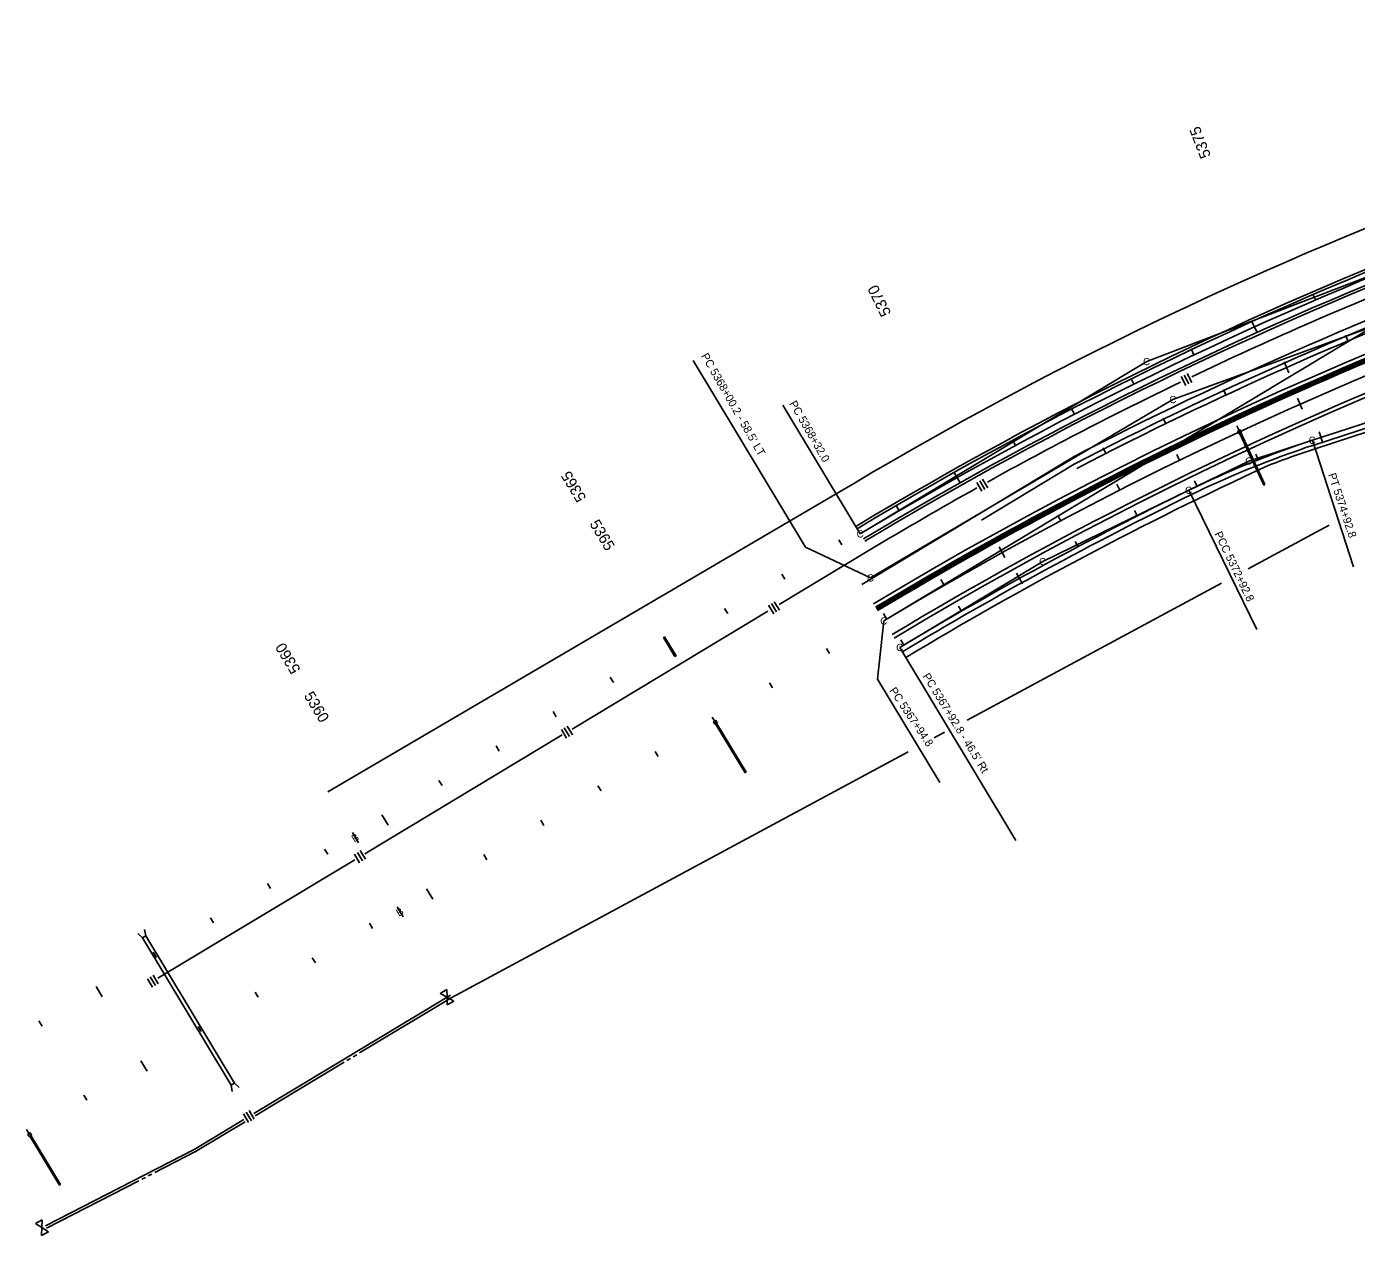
# Model space of a CAD drawing. Extents: x 192699 to 285914, y 194342 to 233219.
# Drawn here: x 279535 to 281530, y 219269 to 221082 of the extents above; entities that cross this region are included whole.
import ezdxf

# ---------------------------------------------------------------- set-up
doc = ezdxf.new("R2010")
doc.units = 0
for name, color, linetype in [('CENT LINE', 7, 'Continuous'), ('CONCRETE', 7, 'Continuous'), ('CURVE DATA', 7, 'Continuous'), ('CURVE LINE', 7, 'Continuous'), ('DRAINAGE', 7, 'Continuous'), ('R-W - CofA', 7, 'Continuous'), ('ROAD', 7, 'Continuous'), ('SHOULDER', 7, 'Continuous'), ('STATIONING1', 7, 'Continuous'), ('STATIONING2', 7, 'Continuous'), ('TEXT', 7, 'Continuous'), ('WRSF', 7, 'Continuous')]:
    doc.layers.add(name, color=color, linetype=linetype)

msp = doc.modelspace()

# ---------------------------------------------------------------- linework, layer by layer
at = {"layer": 'CENT LINE'}
msp.add_line((281463.6, 220461.7), (281631, 220516.2), dxfattribs=at)
for centre, radius, start, end in [((283775, 215280.8), 5730.1, 87.45001, 121.03334), ((283739.9, 215411.7), 5729.9, 111.03691, 121.03638), ((283775, 215280.8), 5788.6, 110.48527, 117.41024), ((281907.3, 219099.2), 1432.9, 108.0419, 116.0389), ((283775, 215280.8), 5683.6, 116.0585, 121.0333)]:
    msp.add_arc(centre, radius, start, end, dxfattribs=at)
at = {"layer": 'CONCRETE'}
for radius, start in [(5752.1, 107.17179), (5748.1, 107.17184)]:
    msp.add_arc((283775, 215280.8), radius, start, 121.03334, dxfattribs=at)
at = {"layer": 'CURVE LINE'}
for p, q in [((280820.9, 220190.8), (282302.5, 221082.2)), ((281683, 220759.7), (281215.2, 220579.8)), ((281749.1, 220703.3), (281254.5, 220522.9)), ((281215.2, 220579.8), (280785.6, 220321.3)), ((281254.5, 220522.9), (280801.1, 220255.3)), ((281368.3, 220430.6), (281463.6, 220461.7)), ((281278.3, 220386.7), (281368.3, 220430.6)), ((281059.3, 220279.9), (281278.3, 220386.7)), ((280844.9, 220150.9), (281059.3, 220279.9))]:
    msp.add_line(p, q, dxfattribs=at)
at = {"layer": 'DRAINAGE'}
for p, q in [((281354.3, 220472.3), (281390.7, 220394.4)), ((281356.2, 220473.2), (281392.5, 220395.2)), ((280490.5, 220165.9), (280492.2, 220166.9)), ((280490.5, 220165.9), (280507.5, 220137.6)), ((280492.2, 220166.9), (280509.3, 220138.6)), ((280507.5, 220137.6), (280509.3, 220138.6)), ((280568.5, 220036.5), (280612.9, 219962.8)), ((280570.2, 220037.5), (280614.6, 219963.9)), ((279842, 219494.4), (279709, 219715.5)), ((279847.1, 219497.5), (279714.1, 219718.6)), ((279540.2, 219417.9), (279584.6, 219344.2)), ((279542, 219418.9), (279586.3, 219345.2))]:
    msp.add_line(p, q, dxfattribs=at)
for points in [[(281353.4, 220471.9), (281357.1, 220473.6), (281355.4, 220477.2), (281351.7, 220475.5)], [(280567.7, 220036), (280571.1, 220038.1), (280569, 220041.5), (280565.6, 220039.4)], [(279539.4, 219417.4), (279542.8, 219419.4), (279540.8, 219422.9), (279537.3, 219420.8)]]:
    msp.add_lwpolyline(points, close=True, dxfattribs=at)
for points in [[(281390.7, 220394.4), (281392.5, 220395.2)], [(280612.9, 219962.8), (280614.6, 219963.9)], [(279702, 219721.9), (279709, 219715.5)], [(279712.4, 219727.7), (279714.2, 219718.4)], [(279714.2, 219718.4), (279709, 219715.5)], [(279842, 219494.4), (279847.2, 219497.4)], [(279843.8, 219485.1), (279842, 219494.4)], [(279854.2, 219491), (279847.2, 219497.4)], [(279584.6, 219344.2), (279586.3, 219345.2)]]:
    msp.add_lwpolyline(points, dxfattribs=at)
at = {"layer": 'R-W - CofA'}
for p, q in [((281271.2, 220559.5), (281278.2, 220546.2)), ((281275.6, 220561.8), (281282.6, 220548.5)), ((281266.7, 220557.2), (281273.7, 220543.8)), ((280964.7, 220401), (280972.4, 220388.1)), ((280969, 220403.5), (280976.7, 220390.6)), ((279987.4, 219934.3), (280749.6, 220381.3)), ((280960.4, 220398.4), (280968.1, 220385.5)), ((281488.7, 220334.3), (281367.4, 220269)), ((280664.1, 220215.5), (280800.1, 220297.3)), ((281327.4, 220247.5), (280945.7, 220042)), ((280656.7, 220219.6), (280664.5, 220206.7)), ((280353.4, 220028.5), (280647.2, 220205.3)), ((280648.1, 220214.5), (280655.9, 220201.6)), ((280652.4, 220217.1), (280660.2, 220204.2)), ((280337.5, 220027.7), (280345.3, 220014.8)), ((280341.8, 220030.3), (280349.6, 220017.4)), ((280346.1, 220032.9), (280353.9, 220020)), ((280912.1, 220023.8), (280896.4, 220015.4)), ((280042.7, 219841.6), (280338.8, 220019.7)), ((280857.5, 219994.4), (280172.9, 219625.9)), ((280027.2, 219841), (280034.9, 219828.1)), ((280031.5, 219843.6), (280039.2, 219830.7)), ((280035.8, 219846.2), (280043.5, 219833.3)), ((279716.5, 219654.1), (279724.2, 219641.2)), ((279720.8, 219656.7), (279728.5, 219643.8)), ((279725.1, 219659.3), (279732.8, 219646.4)), ((280155.8, 219631.9), (280165.8, 219637.9)), ((280166, 219626.3), (280155.8, 219631.9)), ((280165.8, 219637.9), (280166, 219626.3)), ((280166.2, 219614.7), (280166, 219626.3)), ((280166, 219626.3), (280176.1, 219620.6)), ((280176.1, 219620.6), (280166.2, 219614.7)), ((279860.7, 219451.2), (279868.3, 219438.6)), ((279864.9, 219453.7), (279872.6, 219441.1)), ((279869.2, 219456.3), (279876.8, 219443.6)), ((279548.7, 219286.9), (279559, 219292.2)), ((279558.4, 219280.7), (279548.7, 219286.9)), ((279559, 219292.2), (279558.4, 219280.7)), ((279557.9, 219269.1), (279558.4, 219280.7)), ((279568.2, 219274.4), (279557.9, 219269.1)), ((279558.4, 219280.7), (279568.2, 219274.4))]:
    msp.add_line(p, q, dxfattribs=at)
for points in [[(281282.7, 220557), (281282.7, 220557)], [(280976.3, 220399.2), (280976.3, 220399.2)], [(280664.1, 220215.3), (280664.1, 220215.3)], [(280353.4, 220028.5), (280353.4, 220028.5)], [(280043.1, 219841.8), (280043.1, 219841.8)], [(279732.4, 219654.9), (280027.6, 219832.5)], [(279732.4, 219654.9), (279732.4, 219654.9)], [(279876.3, 219452), (280171, 219629.2)], [(280034.8, 219542.7), (280173, 219625.9)], [(279878.4, 219448.6), (280011.6, 219528.8)], [(280015.9, 219531.4), (280021.1, 219534.5)], [(280025.3, 219537), (280030.5, 219540.1)], [(279563.6, 219283.3), (279786.9, 219398.1), (279861.2, 219442.9)], [(279727.7, 219363.3), (279788.8, 219394.7), (279863.2, 219439.5)], [(279565.4, 219279.8), (279703.7, 219350.9)], [(279708.1, 219353.2), (279713.5, 219356)], [(279717.9, 219358.3), (279723.3, 219361)]]:
    msp.add_lwpolyline(points, dxfattribs=at)
for radius, start, end in [(5799.9, 111.03691, 121.03638), (5701.9, 111.7892, 115.5267), (5701.9, 115.717, 118.9921), (5701.9, 119.1747, 121.0364)]:
    msp.add_arc((283739.9, 215411.7), radius, start, end, dxfattribs=at)
at = {"layer": 'ROAD'}
for p, q in [((281465.9, 220454.6), (281633.3, 220509.1)), ((280967.5, 220342), (281106.4, 220426.1))]:
    msp.add_line(p, q, dxfattribs=at)
for centre, radius, start, end in [((283775, 215280.8), 5760.1, 87.45001, 121.03334), ((283775, 215280.8), 5700.1, 87.45, 121.0333), ((283765.6, 215359.2), 5797.2, 110.98651, 120.98597), ((283765.6, 215359.2), 5779.2, 110.98635, 120.98581), ((283775, 215280.8), 5796.1, 110.48527, 117.41317), ((281907.3, 219099.2), 1425.4, 108.0419, 116.0389), ((283775, 215280.8), 5676.1, 116.0585, 121.0333)]:
    msp.add_arc(centre, radius, start, end, dxfattribs=at)
at = {"layer": 'SHOULDER'}
for p, q in [((281467.7, 220448.8), (281635.2, 220503.4)), ((280962.4, 220350.5), (281101.3, 220434.6)), ((280787.9, 220245.6), (280962.4, 220350.6))]:
    msp.add_line(p, q, dxfattribs=at)
for centre, radius, start, end in [((283775, 215280.8), 5706.1, 103.7551, 121.0333), ((283775, 215280.8), 5754.1, 106.67387, 121.03334), ((283765.6, 215359.2), 5801.2, 110.98651, 120.98597), ((283765.6, 215359.2), 5775.2, 110.98635, 120.98581), ((283775, 215280.8), 5806.1, 109.68815, 117.41317), ((281907.3, 219099.2), 1419.4, 108.0419, 111.0954), ((283775, 215280.8), 5666.1, 114.8208, 121.0333)]:
    msp.add_arc(centre, radius, start, end, dxfattribs=at)
at = {"layer": 'STATIONING1'}
for p, q in [((281464.5, 220680.3), (281468.2, 220672.1)), ((281372.9, 220639.8), (281380.6, 220623.5)), ((281513.3, 220619.1), (281516.7, 220610.7)), ((280535, 220581.4), (280703.5, 220301.4)), ((281282.1, 220597.7), (281286, 220589.6)), ((281421.5, 220579.2), (281428.5, 220562.6)), ((281191.9, 220554), (281196, 220546)), ((281330.3, 220537.8), (281333.9, 220529.5)), ((281441.5, 220525), (281448.5, 220508.4)), ((280669.6, 220514.1), (280785.6, 220321.3)), ((281102.6, 220508.7), (281106.8, 220500.8)), ((281239.8, 220494.8), (281243.6, 220486.6)), ((281350.4, 220483.5), (281354.1, 220475.3)), ((281014, 220461.9), (281018.4, 220454.1)), ((281463.6, 220461.7), (281525.3, 220272)), ((281473.7, 220474.5), (281479.3, 220457.3)), ((281150.1, 220450.2), (281154.1, 220442.1)), ((281260.1, 220440.5), (281263.9, 220432.3)), ((281378.9, 220440.9), (281382.3, 220432.5)), ((280926.3, 220413.6), (280935.3, 220398)), ((281286.6, 220400.7), (281290.6, 220392.6)), ((281170.5, 220395.8), (281174.4, 220387.7)), ((281278.3, 220386.7), (281380.2, 220178)), ((280839.5, 220363.7), (280844.1, 220356)), ((281081.7, 220349.6), (281085.8, 220341.6)), ((281196.9, 220356.2), (281201, 220348.2)), ((280703.5, 220301.4), (280801.1, 220255.3)), ((280753.6, 220312.5), (280758.2, 220304.8)), ((280993.7, 220301.9), (281002.2, 220286)), ((281108, 220310), (281112.2, 220302.1)), ((280667.9, 220261), (280672.5, 220253.3)), ((281020, 220262.3), (281028.7, 220246.6)), ((280906.6, 220252.7), (280911, 220244.8)), ((280582.2, 220209.4), (280586.8, 220201.7)), ((280820.4, 220201.9), (280824.9, 220194.1)), ((280932.7, 220213.1), (280937.2, 220205.3)), ((280846.4, 220162.3), (280851.1, 220154.6)), ((280496.6, 220157.8), (280505.8, 220142.4)), ((280735, 220149.6), (280739.7, 220141.9)), ((280410.8, 220106.3), (280415.5, 220098.6)), ((280649.3, 220098.1), (280654, 220090.4)), ((280325.2, 220054.7), (280329.8, 220047)), ((280563.7, 220046.4), (280573, 220031)), ((280239.5, 220003.2), (280244.1, 219995.5)), ((280478, 219995), (280482.6, 219987.2)), ((280153.8, 219951.6), (280158.4, 219943.9)), ((280392.3, 219943.4), (280396.9, 219935.7)), ((280068.1, 219900), (280077.4, 219884.6)), ((280306.6, 219891.8), (280311.2, 219884.1)), ((280220.9, 219840.3), (280225.6, 219832.6)), ((280135.2, 219788.7), (280144.5, 219773.3))]:
    msp.add_line(p, q, dxfattribs=at)
for points in [[(280091, 219762.1), (280095.7, 219754.4)], [(280091, 219762.1), (280100.3, 219746.7)], [(280049.6, 219737.2), (280054.2, 219729.5)], [(279963.9, 219685.6), (279968.5, 219677.9)], [(279878.2, 219634.1), (279882.8, 219626.3)], [(279792.5, 219582.5), (279797.1, 219574.8)], [(279706.8, 219530.9), (279716.1, 219515.5)], [(279621.1, 219479.4), (279625.8, 219471.7)], [(279535.4, 219427.8), (279540.1, 219420.1)]]:
    msp.add_lwpolyline(points, dxfattribs=at)
at = {"layer": 'STATIONING2'}
for points in [[(280024, 219873.5), (280028.6, 219865.8)], [(280024, 219873.5), (280033.3, 219858.1)], [(279982.4, 219848.5), (279987.1, 219840.8)], [(279896.7, 219796.9), (279901.4, 219789.2)], [(279811, 219745.4), (279815.7, 219737.7)], [(279725.4, 219693.8), (279730, 219686.1)], [(279639.7, 219642.3), (279649, 219626.9)], [(279554, 219590.7), (279558.6, 219583)]]:
    msp.add_lwpolyline(points, dxfattribs=at)
at = {"layer": 'TEXT'}
for p, q in [((280820.9, 220190.8), (280811.4, 220103.3)), ((280844.9, 220150.9), (281019, 219861.5)), ((280811.4, 220103.3), (280904.7, 219948.3))]:
    msp.add_line(p, q, dxfattribs=at)
at = {"layer": 'WRSF'}
msp.add_arc((283775, 215280.8), 5750.1, 107.17182, 121.03334, dxfattribs=at)

# ---------------------------------------------------------------- texts
at = {"layer": 'CURVE DATA'}
for s, rotation, p in [('C', 3.0667, (281210, 220574.1)), ('C', 3.0667, (281249.4, 220517.1)), ('C', 3.0667, (281458.4, 220456)), ('C', 3.0667, (281363.2, 220424.9)), ('C', 3.0667, (281273.1, 220381)), ('C', 3.0667, (280780.5, 220315.6)), ('C', 3.0667, (281054.1, 220274.2)), ('C', 3.0667, (280796, 220249.5)), ('C', 3.0667, (280815.8, 220185)), ('C', 3.0667, (280839.8, 220145.2)), ('B', 31.0333, (280026.8, 219858.4)), ('B', 31.0333, (280093.8, 219747))]:
    msp.add_text(s, height=10.8, rotation=rotation, dxfattribs=at).set_placement(p)
at = {"layer": 'STATIONING1'}
for s, rotation, p in [('5375', 111.0333, (281311.7, 220888.3)), ('5370', 116.0333, (280832.3, 220652.3)), ('5365', 121.0333, (280375.4, 220375.3)), ('5360', 121.0333, (279946.9, 220117.7))]:
    msp.add_text(s, height=16.5, rotation=rotation, dxfattribs=at).set_placement(p)
at = {"layer": 'STATIONING2'}
for s, p in [('5365', (280379.1, 220336.4)), ('5360', (279950.7, 220078.6))]:
    msp.add_text(s, height=16.5, rotation=301.0333, dxfattribs=at).set_placement(p)
at = {"layer": 'TEXT'}
for s, rotation, p in [("PC 5368+00.2 - 58.5' LT", 299.8875, (280546.5, 220588.2)), ('PC 5368+32.0', 299.8875, (280678.8, 220516.8)), ('PT 5374+92.8', 288.2625, (281487, 220410.3)), ('PCC 5372+92.8', 295.7996, (281316.4, 220321.5)), ("PC 5367+92.8 - 46.5' Rt", 301.6162, (280878.6, 220107.9)), ('PC 5367+94.8', 303.8282, (280828.7, 220086.3))]:
    msp.add_text(s, height=12, rotation=rotation, dxfattribs=at).set_placement(p)

doc.saveas('drawing.dxf')
